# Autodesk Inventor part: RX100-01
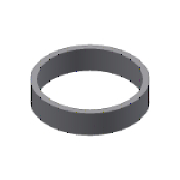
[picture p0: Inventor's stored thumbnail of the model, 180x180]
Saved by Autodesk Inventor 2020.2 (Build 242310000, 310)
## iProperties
Manager: www.cadconsulting.pl
Company: Fabian Stasiak CAD Consulting
IsCustomPart: 0
Created: 2014-07
Part Number: RX100-01
Material: Ogólny
Document SubType Name: Modeling
Standard: DIN EN 1661
Designer: F.Stasiak
Manufacturer: KeroX
Standards Organization: DIN
Language: pl-PL
Size Designation: 40
Categories: <MemberInstance><Categories><Category DisplayName="Rury cienko- i grubościenne" InternalName="4347fa0f-2144-441d-94cd-e3e15c92b736" Mnemonic="TUBEANDPIPE"><Cate
Density: 1 g/cm^3
Appearance: Domyślna
Catalog Web Link: www.expertbooks.pl
Author: F.Stasiak
Subject: Zbiór ćwiczeń. Autodesk Inventor 2020. Kurs Professional
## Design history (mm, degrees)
sketch "Szkic1"
  geometry: C1 r 20 at (0, 0); C2 r 22.5 at (0, 0); 1 further point
  constraints: 2 centre point, 2 coincident
  dimensions: "ID" = 40 diameter of C1; "OD" = 45 diameter of C2
extrude "Wyciągnięcie proste1" new body sketch "Szkic1" taper "d3" = 0 deg; distance "L" = 10
node "Punkt konstrukcyjny1"
node "Punkt konstrukcyjny2"
node "Oś konstrukcyjna1"
node "Oś konstrukcyjna2"
node "Bryła1"
